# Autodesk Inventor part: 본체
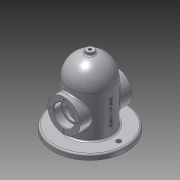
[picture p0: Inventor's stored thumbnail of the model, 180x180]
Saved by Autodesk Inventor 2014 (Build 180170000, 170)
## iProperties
Created: 2019-11
Part Number: 본체
Material: 알루미늄 6061
Document SubType Name: Modeling
Designer: OA55
Density: 2.71 g/cm^3
Appearance: 알루미늄 - 평지
Mass: 1110.22 g
Surface Area: 883.664 cm^2
Volume: 409.676 cm^3
Author: OA55
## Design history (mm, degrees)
sketch "스케치1"
  geometry: C1 r 40 at (0, 0); 1 further point
  constraints: 1 centre point, 1 coincident
  dimensions: "d0" = 80 diameter of C1
extrude "돌출1" new body sketch "스케치1" distance "d1" = 80; taper "d2" = 0 deg
sketch "스케치2"
  geometry: C1 r 40 at (0, 0) reference; C2 r 70 at (0, 0)
  constraints: 1 centre point, 1 coincident
  dimensions: "d3" = 140 diameter of C2
extrude "돌출2" join sketch "스케치2" distance "d4" = 10; taper "d5" = 0 deg
node "작업 평면1"
sketch "스케치3"
  geometry: L1 (0, -40)-(0, -70) reference; L2 (0, -70)-(-10, -70) reference; L3 (-10, -70)-(-10, 70) reference; L4 (-10, 70)-(0, 70) reference; L5 (0, 70)-(0, 40) reference; L6 (0, 40)-(80, 40) reference; L7 (80, 40)-(80, -40) reference; L8 (80, -40)-(0, -40) reference; L9 (80, 0)-(120, 0); 2 further points; 1 other entity
  constraints: 4 end point, 1 coincident, 1 midpoint, 1 parallel, 1 vertical, 4 other
  dimensions: "d7" = 40 distance of L9.end L9.start
revolve "회전1" sketch "스케치3" stored, may be unused: angle "d8" = 90 deg
node "작업 평면2"
sketch "스케치4"
  geometry: L1 (-70, -10)-(70, -10) reference; C1 r 31 at (0, 40); 1 further point
  constraints: 1 centre point, 1 vertical alignment
  dimensions: "d10" = 62 diameter of C1; "d11" = 50 distance from line of C1.centre L1
extrude "돌출3" join sketch "스케치4" stored distance "d12" = 100; taper "d13" = 0 deg
sketch "스케치5"
  geometry: C1 r 31 at (0, 0) reference; C2 r 20 at (0, 0); 1 further point
  constraints: 1 centre point, 1 coincident
  dimensions: "d14" = 40 diameter of C2
extrude "돌출4" cut sketch "스케치5" distance "d15" = 15; taper "d16" = 0 deg
sketch "스케치6"
  geometry: C1 r 31 at (0, 0) reference; C2 r 20 at (0, 0); 1 further point
  constraints: 1 centre point, 1 coincident
  dimensions: "d17" = 40 diameter of C2
extrude "돌출5" cut sketch "스케치6" distance "d18" = 15; taper "d19" = 0 deg
sketch "스케치7"
  geometry: C1 r 20 at (0, 0) reference; C2 r 16.5 at (0, 0); 1 further point
  constraints: 1 centre point, 1 coincident
  dimensions: "d20" = 33 diameter of C2
extrude "돌출6" cut sketch "스케치7" stored distance "d21" = 15; taper "d22" = 0 deg
node "작업 평면5"
sketch "스케치10"
  geometry: C1 r 7.5 at (0, 0); 1 further point
  constraints: 1 centre point, 1 coincident
  dimensions: "d27" = 15 diameter of C1
extrude "돌출7" join sketch "스케치10" stored distance "d28" = 15; taper "d29" = 0 deg
node "작업 평면6"
sketch "스케치11"
  geometry: L1 (-70, -10)-(70, -10) reference; L2 (0, -10)-(0, 80); L3 (-30, -10)-(-30, 80); L4 (-30, 80)-(0, 80); 1 further point
  constraints: 6 end point, 2 perpendicular, 1 midpoint, 1 parallel, 1 point on line
  dimensions: "d31" = 90 distance of L2.start L2.end; "d32" = 60 diameter of L3 L2
revolve "회전2" sketch "스케치11" stored, may be unused: angle "d33" = 90 deg
sketch "스케치12"
  geometry: L1 (-30, 80)-(30, 80) reference; L2 (40, 0)-(40, 80) reference; L3 (30, 80)-(30, -10) reference; L4 (0, 80)-(0, 110); A1 r 40 centre (0, 80) between (40, 80) and (-40, 80) reference; 2 further points; 1 other entity
  constraints: 4 end point, 1 coincident, 1 horizontal, 1 parallel, 4 other
  dimensions: "d34" = 30 distance of L4.end L4.start
revolve "회전3" sketch "스케치12" stored, may be unused: angle "d35" = 90 deg
sketch "스케치13"
  geometry: C1 r 7.5 at (0, 0) reference; 1 further point
  constraints: 1 coincident
hole "구멍1" sketch "스케치13" at (0, 0) diameter "d36" = 5.188; stored, may be unused: countersink angle "d40" = 90 deg, drill point angle "d42" = 0 deg; dims "d37" = 15, "d38" = 4, "d39" = 2, "d41" = 15
sketch "스케치14"
  geometry: L1 (0, 0)-(-55, 0); L2 (0, 0)-(55, 0); C1 r 40 at (0, 0) reference; C2 r 4.5 at (55, 0); C3 r 4.5 at (-55, 0); A1 r 55 centre (0, 0) between (-55, 0) and (55, 0)
  constraints: 4 end point, 3 centre point, 3 coincident, 2 point on circle, 1 collinear, 1 horizontal
  dimensions: "d43" = 110 diameter of A1; "d44" = 9 diameter of C2; "d45" = 9 diameter of C3
extrude "돌출8" cut sketch "스케치14" stored distance "d46" = 15; taper "d47" = 0 deg
node "작업 평면7"
sketch "스케치15"
  geometry: L1 (-10, 70)-(-10, -70) reference; 2 further points
  constraints: 1 horizontal alignment, 1 other
  dimensions: "d48" = 50 distance from line of L1 point (40, 0)
feature "엠보싱1" sketch "스케치15" dims "d2" = 0, "d49" = 0.5, "d50" = 0
sketch "스케치17" dims "d52" = 52
  geometry: L1 (0, 0)-(0, 26); C1 r 31 at (0, 0) reference; 2 further points
  constraints: 2 coincident, 2 end point, 1 vertical, 1 vertical alignment, 2 other
hole "구멍2" sketch "스케치17" at (0, 26) diameter "d53" = 3.242; stored, may be unused: countersink angle "d57" = 90 deg, drill point angle "d59" = 118 deg; dims "d54" = 8, "d55" = 4, "d56" = 2, "d58" = 10
node "작업 평면9"
fillet "모깎기1" dims "d63" = 3
chamfer "모따기1" distance "d64" = 1; stored, may be unused: second distance "d65" = 2, angle "d66" = 45 deg
fillet "모깎기2" dims "d67" = 0.3
node "솔리드1"
pattern_circular "원형 패턴1" dims angle "d61" = 360 deg
mirror "대칭1"
node "절단 모서리 투영1"
other parameters: "d6" = 0, "d9" = 0, "d26" = -135, "d30" = 0
